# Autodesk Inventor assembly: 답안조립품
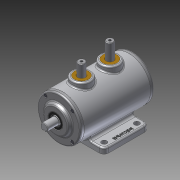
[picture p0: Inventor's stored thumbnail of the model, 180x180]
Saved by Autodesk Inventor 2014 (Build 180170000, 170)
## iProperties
Created: 2014-12
Part Number: 답안조립품
Document SubType Name: Assembly
Designer: Owner
Author: Owner
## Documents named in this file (10)
- C:\Users\Owner\Desktop\441223V1010\답안조립품.iam
- C:\Users\Owner\Desktop\441223V1010\M4-소켓머리.ipt
- C:\Users\Owner\Desktop\441223V1010\뒷커버.ipt
- C:\Users\Owner\Desktop\441223V1010\베어링 6203.ipt
- C:\Users\Owner\Desktop\441223V1010\본체.ipt
- C:\Users\Owner\Desktop\441223V1010\부시.ipt
- C:\Users\Owner\Desktop\441223V1010\슬라이더.ipt
- C:\Users\Owner\Desktop\441223V1010\앞커버.ipt
- C:\Users\Owner\Desktop\441223V1010\오일실.ipt
- C:\Users\Owner\Desktop\441223V1010\축.ipt
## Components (11 placed, 3 different names)
1. 7-베어링 6203:1
2. 8-오일실:1
3. 7-베어링 6203:2
4. 9-M4-소켓머리:5
5. 9-M4-소켓머리:6
6. 9-M4-소켓머리:7
7. 9-M4-소켓머리:8
8. 9-M4-소켓머리:9
9. 9-M4-소켓머리:10
10. 9-M4-소켓머리:11
11. 9-M4-소켓머리:12
